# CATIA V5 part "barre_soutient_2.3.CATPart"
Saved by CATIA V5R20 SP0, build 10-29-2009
Part number: barre_soutient_2.3
Bounding box of the stored display mesh (mm): x 505.778 to 2805.778, y 1226.082 to 1295.849, z -486.864 to -416.883
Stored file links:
  C:\Users\Mike-7\Desktop\MMS_GR3\bfoltzer\CFAO_bfoltzer\barre_soutient_2.3.CATPart
  D:\ecole\thinkmotion\Eolienne.CATProduct
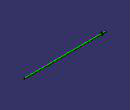
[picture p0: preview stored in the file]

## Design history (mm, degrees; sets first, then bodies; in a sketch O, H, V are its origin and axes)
Set1
  Plane1 "plan dessin": linked copy from another document
  Point1 to Point4: linked copy from another document
  Line1 "axe de rotation": linked copy from another document
Body1 (main body)
  Sketch1 on Plane1, origin (0, 624.7545, -168.3165), H (-1, 0, 0), V (0, -0.9134, 0.4071)
    point P1 (-505.7782, -716.5406)
    line L1 (-505.7782, -716.5406) -> (-2805.7782, -716.5406)
    line L2 (-2805.7782, -716.5406) -> (-2805.7782, -696.5406)
    line L3 (-2805.7782, -696.5406) -> (-505.7782, -696.5406)
    line L4 (-505.7782, -696.5406) -> (-505.7782, -716.5406)
    point P3 (-2805.7782, -696.5406)
    reference projected point E1 (-505.7782, -716.5406) from Point1
    reference projected point E2 (-2805.7782, -696.5406) from Point2
    horizontal: L1 H, L3 H
    vertical: L2 V, L4 V
    coincidence: P1 E1, P3 E2
  Shaft1: profile Sketch1, axis Sketch1.L3, angle 360
  Sketch2 on Plane1, origin (0, 624.7545, -168.3165), H (-1, 0, 0), V (0, -0.9134, 0.4071)
    point P1 (-605.7782, -661.5406)
    line L1 (-605.7782, -661.5406) -> (-625.7782, -661.5406)
    line L2 (-625.7782, -661.5406) -> (-625.7782, -676.5406)
    line L3 (-625.7782, -676.5406) -> (-605.7782, -676.5406)
    line L4 (-605.7782, -676.5406) -> (-605.7782, -661.5406)
    point P3 (-625.7782, -676.5406)
    reference projected point E1 (-625.7782, -676.5406) from Point3
    reference projected point E2 (-605.7782, -661.5406) from Point4
    horizontal: L1 H, L3 H
    vertical: L2 V, L4 V
    coincidence: P3 E1, P1 E2
  Shaft2: profile Sketch2, axis Line1, angle 360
